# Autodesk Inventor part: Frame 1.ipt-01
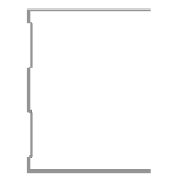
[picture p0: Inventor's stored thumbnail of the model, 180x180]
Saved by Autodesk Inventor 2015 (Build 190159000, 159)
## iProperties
Created: 2015-04
Part Number: Frame 1.ipt-01
Material: Aluminum 6061
Document SubType Name: Modeling
Standard: Unnamed
Designer: suporte
Language: en-US
Size Designation: (Unnamed 1)
Categories: <MemberInstance><Categories><Category DisplayName="Structural Shapes" InternalName="089c4875-fa83-4c05-b084-43b9cc11f5ed" Mnemonic="GRDR"><CategoryParameter Dis
Density: 2.7 g/cm^3
Appearance: Aluminum - Flat
_CCFamilyMember: 1
_CCFamilyDisplayName: Frame 1
_FrameMemberDoc: Frame Member File
_Version: 15.0.0
_GetPNFromCC: 1
IsCustomPart: 1
G_L: 2100,000 mm
G_W: 70,000 mm
G_H: 75,000 mm
Author: suporte
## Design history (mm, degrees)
node "Start Plane"
node "End Plane"
sketch "Sketch"
  geometry: L1 (34.6, 37.5)-(34.6, 36.7); L2 (34.6, 36.7)-(-34.6, 36.7); L3 (-34.6, -36.7)-(34.6, -36.7); L4 (34.6, -36.7)-(34.6, -37.5); L5 (34.6, -37.5)-(-35.4, -37.5); L6 (-35.4, 37.5)-(34.6, 37.5); L7 (-34.6, 36.7)-(-34.6, 31.7); L8 (-34.6, 31.7)-(-33.4, 30.5); L9 (-33.4, 30.5)-(-33.4, 10.746); L10 (-33.4, 10.746)-(-34.6, 9.546); L11 (-34.6, 9.546)-(-34.6, -9.546); L12 (-34.6, -9.546)-(-33.4, -10.746); L13 (-33.4, -10.746)-(-33.4, -30.5); L14 (-33.4, -30.5)-(-34.6, -31.7); L15 (-34.6, -31.7)-(-34.6, -36.7); L16 (-35.4, -37.5)-(-35.4, -31.369); L17 (-35.4, -31.369)-(-34.2, -30.169); L18 (-34.2, -30.169)-(-34.2, -11.077); L19 (-34.2, -11.077)-(-35.4, -9.877); L20 (-35.4, -9.877)-(-35.4, 9.877); L21 (-35.4, 9.877)-(-34.2, 11.077); L22 (-34.2, 11.077)-(-34.2, 30.169); L23 (-34.2, 30.169)-(-35.4, 31.369); L24 (-35.4, 31.369)-(-35.4, 37.5); L25 (-35.4, 0)-(30.37, 0); 3 further points
  constraints: 50 end point, 10 point on line, 9 parallel, 5 perpendicular, 4 equal length, 3 midpoint, 3 vertical, 2 vertical alignment, 1 collinear, 1 horizontal, 1 horizontal alignment
  dimensions: "d3" = 0.8 distance of L1.start L1.end; "d5" = 75 distance between parallel lines of L5 L6; "d6" = 0.8 distance between parallel lines of L24 L7; "d7" = 0.8 distance between parallel lines of L8 L23; "d8" = 0.8 distance between parallel lines of L22 L9; "d9" = 0.8 distance between parallel lines of L17 L14; "d10" = 0.8 distance between parallel lines of L13 L18; "d11" = 0.8 distance between parallel lines of L12 L19; "d12" = 0.8 distance between parallel lines of L21 L10; "d13" = 5 distance of L2.end L7.end; "d15" = 135 deg angle of L9 L8; "d16" = 2 distance between parallel lines of L24 L9; "d17" = 70 distance of L6.start L1.start
extrude "Body" join sketch "Sketch" stored distance "d24" = 0.13; taper "d25" = 0 deg
node "Driven Length"
  sketch "Sketch8"
    geometry: L1 (0, 0)-(10, 0) reference
    constraints: 2 end point, 1 horizontal
  workplane "Work Plane6"
  sketch "Sketch9"
    geometry: L1 (-2, 0)-(12, 0) reference; L2 (-2, 2100)-(12, 2100) reference
    dimensions: "d27" = 2100 distance between parallel lines of L1 L2 (derived)
body "Solid1"
other parameters: "G_OFFSET_START" = 0 [user parameter; used in 1 equation term], "G_OFFSET_END" = 0 [user parameter; used in 1 equation term], "d22" = 0 (computed from G_OFFSET_START), "G_L" = 2100 (= d27) [user parameter], "d32" = 90 deg
